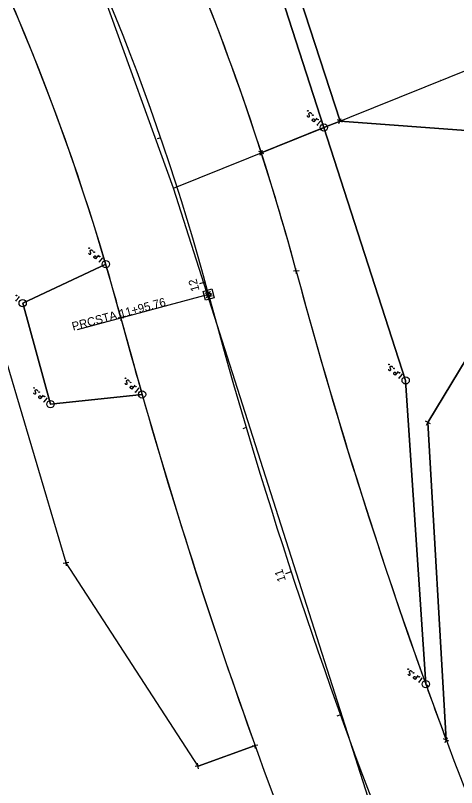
# Model space of a CAD drawing. Extents: x 2392034 to 2394211, y 184331 to 186655.
# Drawn here: x 2392791 to 2392936.9, y 185125.1 to 185380.6 of the extents above; entities that cross this region are included whole.
import ezdxf

# ---------------------------------------------------------------- set-up
doc = ezdxf.new("R2010")
doc.units = 0
for name, color, linetype in [('V-ROAD-SIGN', 7, 'Continuous'), ('V-SITE-MAIL', 7, 'Continuous'), ('V-SITE-MISC', 7, 'Continuous'), ('V-SURV-ANNO', 7, 'Continuous'), ('V-TOPO-ANNO', 7, 'Continuous'), ('V-TOPO-TINN', 7, 'Continuous'), ('V-TOPO-USER', 7, 'Continuous'), ('V-TOPO-WSHD', 7, 'Continuous'), ('V-UTIL-NGAS-STRC', 7, 'Continuous'), ('V-UTIL-SSWR-STRC', 7, 'Continuous'), ('V-UTIL-STRM-STRC', 7, 'Continuous')]:
    doc.layers.add(name, color=color, linetype=linetype)

msp = doc.modelspace()

# ---------------------------------------------------------------- linework, layer by layer
for p, q in [((2392854.78, 185288.58), (2392854.78, 185288.58)), ((2392854.78, 185288.58), (2392854.78, 185288.58)), ((2392854.87, 185288.23), (2392854.87, 185288.23)), ((2392855.06, 185287.51), (2392855.06, 185287.51)), ((2392861.73, 185263.39), (2392861.73, 185263.39)), ((2392832.87, 185255.19), (2392832.87, 185255.19))]:
    msp.add_line(p, q)
at = {"layer": 'Defpoints'}
for centre in [(2392885.39, 185367.2), (2392931.57, 185359.02), (2392903.47, 185311.11), (2392802.61, 185251.97), (2392807.77, 185199.41)]:
    msp.add_circle(centre, 0.05, dxfattribs=at)
at = {"layer": 'V-ROAD-SIGN'}
for centre, radius, start, end in [((2392082.2, 185080.9), 830, 15.02013, 45.41914), ((2392082.2, 185080.9), 770, 15.02013, 44.49359), ((2394545.08, 185741.75), 1720, 195.02013, 207.9775), ((2394545.08, 185741.75), 1780, 195.02013, 207.9775)]:
    msp.add_arc(centre, radius, start, end, dxfattribs=at)
at = {"layer": 'V-SITE-MAIL'}
for centre, radius, start, end in [((2392082.2, 185080.9), 800, 15.02013, 44.49359), ((2394545.08, 185741.75), 1750, 195.02013, 207.9775)]:
    msp.add_arc(centre, radius, start, end, dxfattribs=at)
at = {"layer": 'V-SITE-MISC'}
msp.add_line((2392854.87, 185288.23), (2392811.41, 185276.56), dxfattribs=at)
msp.add_circle((2392854.87, 185288.23), 0.6, dxfattribs=at)
at = {"layer": 'V-SURV-ANNO'}
for p, q in [((2392839.05, 185340.1), (2392837.92, 185339.71)), ((2392853.76, 185292.32), (2392851.83, 185291.79)), ((2392867.31, 185244.19), (2392866.16, 185243.85)), ((2392882.21, 185196.46), (2392880.31, 185195.84)), ((2392898.46, 185149.18), (2392897.33, 185148.77))]:
    msp.add_line(p, q, dxfattribs=at)
at = {"layer": 'V-TOPO-ANNO'}
for p, q in [((2392843.3, 185323.45), (2392806.01, 185426.43)), ((2392843.3, 185323.45), (2392806.01, 185426.43)), ((2392843.3, 185323.45), (2392979.31, 185378.26)), ((2392843.3, 185323.45), (2392979.31, 185378.26)), ((2392921.32, 185078.99), (2392843.3, 185323.45))]:
    msp.add_line(p, q, dxfattribs=at)
at = {"layer": 'V-TOPO-TINN'}
msp.add_line((2392854.87, 185288.23), (2392854.87, 185288.23), dxfattribs=at)
for points in [[(2392887.45, 185347.41), (2392887.45, 185347.38), (2392887.46, 185347.34), (2392887.51, 185347.24), (2392887.59, 185347.14), (2392887.65, 185347.08), (2392887.68, 185347.06), (2392887.81, 185347), (2392887.95, 185346.97), (2392888.08, 185347), (2392888.16, 185347.06), (2392888.21, 185347.12), (2392888.26, 185347.21), (2392888.25, 185347.33), (2392888.04, 185348.02), (2392888.03, 185348.09), (2392888.05, 185348.14), (2392888.08, 185348.21), (2392888.13, 185348.27), (2392888.19, 185348.32), (2392888.23, 185348.35), (2392888.29, 185348.39), (2392888.34, 185348.41), (2392888.38, 185348.42), (2392888.43, 185348.43), (2392888.47, 185348.43), (2392888.52, 185348.42), (2392888.56, 185348.41), (2392888.64, 185348.35), (2392888.76, 185348.25), (2392888.81, 185348.16), (2392888.86, 185348), (2392888.88, 185347.89)], [(2392887.67, 185348.9), (2392887.63, 185348.94), (2392887.63, 185348.98), (2392887.63, 185349.04), (2392887.67, 185349.09), (2392887.73, 185349.1), (2392887.77, 185349.1), (2392887.82, 185349.07), (2392887.82, 185349.03), (2392887.82, 185348.97), (2392887.77, 185348.92), (2392887.72, 185348.9), (2392887.67, 185348.9)], [(2392889.32, 185347.47), (2392889.28, 185347.51), (2392889.27, 185347.55), (2392889.28, 185347.61), (2392889.32, 185347.66), (2392889.38, 185347.67), (2392889.42, 185347.67), (2392889.46, 185347.63), (2392889.47, 185347.59), (2392889.46, 185347.53), (2392889.42, 185347.48), (2392889.36, 185347.47), (2392889.32, 185347.47)], [(2392890.7, 185346.55), (2392889.65, 185345.35), (2392889.25, 185345.7), (2392889.22, 185345.74), (2392889.18, 185345.81), (2392889.17, 185345.85), (2392889.16, 185345.89), (2392889.17, 185345.97), (2392889.18, 185346.04), (2392889.23, 185346.13), (2392889.33, 185346.24), (2392889.37, 185346.27), (2392889.44, 185346.32), (2392889.53, 185346.35), (2392889.59, 185346.35), (2392889.63, 185346.35), (2392889.69, 185346.33), (2392889.76, 185346.28), (2392890.16, 185345.94)], [(2392891.88, 185345.53), (2392890.83, 185344.32)], [(2392891.02, 185345.99), (2392890.98, 185346.03), (2392890.97, 185346.07), (2392890.98, 185346.13), (2392891.02, 185346.18), (2392891.07, 185346.2), (2392891.12, 185346.19), (2392891.16, 185346.16), (2392891.17, 185346.12), (2392891.16, 185346.06), (2392891.12, 185346.01), (2392891.06, 185345.99), (2392891.02, 185345.99)], [(2392892.01, 185345.41), (2392891.75, 185345.64)], [(2392890.96, 185344.2), (2392890.7, 185344.44)], [(2392815.16, 185301.96), (2392815.17, 185301.93), (2392815.18, 185301.89), (2392815.23, 185301.8), (2392815.31, 185301.7), (2392815.38, 185301.65), (2392815.4, 185301.63), (2392815.54, 185301.57), (2392815.68, 185301.55), (2392815.8, 185301.58), (2392815.88, 185301.65), (2392815.93, 185301.7), (2392815.98, 185301.8), (2392815.96, 185301.92), (2392815.72, 185302.59), (2392815.71, 185302.67), (2392815.73, 185302.72), (2392815.76, 185302.79), (2392815.8, 185302.85), (2392815.86, 185302.91), (2392815.9, 185302.94), (2392815.96, 185302.97), (2392816.01, 185303), (2392816.05, 185303.01), (2392816.1, 185303.02), (2392816.14, 185303.02), (2392816.19, 185303.02), (2392816.22, 185303), (2392816.31, 185302.95), (2392816.43, 185302.86), (2392816.49, 185302.77), (2392816.55, 185302.62), (2392816.57, 185302.5)], [(2392815.32, 185303.47), (2392815.28, 185303.5), (2392815.27, 185303.54), (2392815.27, 185303.6), (2392815.31, 185303.65), (2392815.37, 185303.67), (2392815.41, 185303.67), (2392815.45, 185303.63), (2392815.46, 185303.59), (2392815.46, 185303.53), (2392815.42, 185303.48), (2392815.36, 185303.46), (2392815.32, 185303.47)], [(2392817.03, 185302.1), (2392816.98, 185302.14), (2392816.97, 185302.18), (2392816.98, 185302.24), (2392817.02, 185302.29), (2392817.07, 185302.31), (2392817.12, 185302.31), (2392817.16, 185302.27), (2392817.17, 185302.23), (2392817.16, 185302.17), (2392817.12, 185302.12), (2392817.07, 185302.1), (2392817.03, 185302.1)], [(2392818.44, 185301.25), (2392817.44, 185300), (2392817.03, 185300.33), (2392817, 185300.37), (2392816.95, 185300.44), (2392816.94, 185300.48), (2392816.93, 185300.52), (2392816.94, 185300.6), (2392816.95, 185300.67), (2392817, 185300.76), (2392817.09, 185300.88), (2392817.13, 185300.91), (2392817.19, 185300.95), (2392817.28, 185301), (2392817.34, 185301), (2392817.38, 185301), (2392817.44, 185300.98), (2392817.52, 185300.94), (2392817.93, 185300.61)], [(2392818.81, 185298.91), (2392818.53, 185299.13)], [(2392819.67, 185300.27), (2392818.67, 185299.02)], [(2392818.78, 185300.7), (2392818.74, 185300.74), (2392818.73, 185300.78), (2392818.74, 185300.84), (2392818.78, 185300.88), (2392818.83, 185300.9), (2392818.87, 185300.9), (2392818.92, 185300.87), (2392818.93, 185300.83), (2392818.92, 185300.77), (2392818.88, 185300.72), (2392818.82, 185300.7), (2392818.78, 185300.7)], [(2392819.8, 185300.16), (2392819.53, 185300.38)], [(2392853.82, 185286.38), (2392853.03, 185289.27), (2392855.92, 185290.07), (2392856.72, 185287.18), (2392853.82, 185286.38)], [(2392856.03, 185287.78), (2392854.1, 185287.25), (2392855.84, 185288.49), (2392853.71, 185288.67), (2392855.64, 185289.2)], [(2392791.32, 185286.01), (2392791.05, 185286.23)], [(2392792.19, 185287.37), (2392791.18, 185286.12)], [(2392791.31, 185287.8), (2392791.27, 185287.84), (2392791.26, 185287.88), (2392791.26, 185287.94), (2392791.3, 185287.99), (2392791.36, 185288.01), (2392791.4, 185288.01), (2392791.45, 185287.97), (2392791.46, 185287.93), (2392791.45, 185287.87), (2392791.41, 185287.82), (2392791.35, 185287.8), (2392791.31, 185287.8)], [(2392792.33, 185287.26), (2392792.05, 185287.48)], [(2392914.31, 185263.5), (2392914.31, 185263.47), (2392914.32, 185263.43), (2392914.38, 185263.33), (2392914.46, 185263.24), (2392914.52, 185263.18), (2392914.55, 185263.16), (2392914.69, 185263.1), (2392914.83, 185263.09), (2392914.95, 185263.12), (2392915.03, 185263.18), (2392915.08, 185263.24), (2392915.12, 185263.34), (2392915.11, 185263.46), (2392914.87, 185264.13), (2392914.86, 185264.21), (2392914.87, 185264.26), (2392914.9, 185264.33), (2392914.95, 185264.39), (2392915.01, 185264.44), (2392915.05, 185264.48), (2392915.1, 185264.51), (2392915.15, 185264.54), (2392915.19, 185264.55), (2392915.24, 185264.56), (2392915.28, 185264.56), (2392915.33, 185264.55), (2392915.37, 185264.54), (2392915.45, 185264.49), (2392915.57, 185264.4), (2392915.63, 185264.31), (2392915.69, 185264.16), (2392915.71, 185264.04)], [(2392914.46, 185265), (2392914.42, 185265.04), (2392914.41, 185265.08), (2392914.42, 185265.14), (2392914.46, 185265.19), (2392914.51, 185265.21), (2392914.55, 185265.21), (2392914.6, 185265.17), (2392914.61, 185265.13), (2392914.6, 185265.07), (2392914.56, 185265.02), (2392914.51, 185265), (2392914.46, 185265)], [(2392916.17, 185263.65), (2392916.13, 185263.68), (2392916.12, 185263.72), (2392916.12, 185263.78), (2392916.16, 185263.83), (2392916.22, 185263.85), (2392916.26, 185263.85), (2392916.31, 185263.81), (2392916.32, 185263.77), (2392916.31, 185263.71), (2392916.27, 185263.66), (2392916.21, 185263.64), (2392916.17, 185263.65)], [(2392827.36, 185260.44), (2392827.32, 185260.47), (2392827.31, 185260.51), (2392827.31, 185260.57), (2392827.35, 185260.62), (2392827.41, 185260.64), (2392827.45, 185260.64), (2392827.49, 185260.6), (2392827.5, 185260.56), (2392827.5, 185260.5), (2392827.46, 185260.45), (2392827.4, 185260.43), (2392827.36, 185260.44)], [(2392917.59, 185262.79), (2392916.6, 185261.54), (2392916.18, 185261.87), (2392916.15, 185261.91), (2392916.1, 185261.98), (2392916.09, 185262.02), (2392916.08, 185262.06), (2392916.09, 185262.14), (2392916.1, 185262.21), (2392916.14, 185262.3), (2392916.24, 185262.42), (2392916.28, 185262.45), (2392916.34, 185262.5), (2392916.43, 185262.54), (2392916.49, 185262.54), (2392916.53, 185262.54), (2392916.59, 185262.52), (2392916.67, 185262.48), (2392917.08, 185262.15)], [(2392917.96, 185260.45), (2392917.68, 185260.67)], [(2392918.82, 185261.82), (2392917.82, 185260.56)], [(2392917.93, 185262.25), (2392917.89, 185262.28), (2392917.88, 185262.32), (2392917.88, 185262.38), (2392917.92, 185262.43), (2392917.98, 185262.45), (2392918.02, 185262.45), (2392918.07, 185262.41), (2392918.08, 185262.37), (2392918.07, 185262.31), (2392918.03, 185262.26), (2392917.97, 185262.25), (2392917.93, 185262.25)], [(2392918.95, 185261.71), (2392918.68, 185261.93)], [(2392827.19, 185258.93), (2392827.19, 185258.9), (2392827.2, 185258.86), (2392827.25, 185258.77), (2392827.33, 185258.67), (2392827.4, 185258.62), (2392827.42, 185258.6), (2392827.56, 185258.53), (2392827.7, 185258.52), (2392827.83, 185258.55), (2392827.91, 185258.61), (2392827.95, 185258.67), (2392828, 185258.76), (2392827.99, 185258.88), (2392827.76, 185259.56), (2392827.74, 185259.63), (2392827.76, 185259.69), (2392827.79, 185259.76), (2392827.84, 185259.82), (2392827.89, 185259.87), (2392827.93, 185259.9), (2392827.99, 185259.94), (2392828.04, 185259.96), (2392828.08, 185259.98), (2392828.13, 185259.99), (2392828.17, 185259.98), (2392828.22, 185259.98), (2392828.26, 185259.97), (2392828.34, 185259.91), (2392828.46, 185259.82), (2392828.52, 185259.73), (2392828.58, 185259.57), (2392828.6, 185259.46)], [(2392830.46, 185258.19), (2392829.45, 185256.95), (2392829.04, 185257.28), (2392829.01, 185257.32), (2392828.96, 185257.39), (2392828.95, 185257.43), (2392828.94, 185257.47), (2392828.95, 185257.55), (2392828.96, 185257.62), (2392829.01, 185257.71), (2392829.1, 185257.83), (2392829.14, 185257.86), (2392829.21, 185257.91), (2392829.3, 185257.95), (2392829.36, 185257.95), (2392829.4, 185257.95), (2392829.46, 185257.93), (2392829.53, 185257.89), (2392829.94, 185257.55)], [(2392829.05, 185259.06), (2392829.01, 185259.09), (2392829, 185259.13), (2392829.01, 185259.19), (2392829.05, 185259.24), (2392829.1, 185259.26), (2392829.14, 185259.26), (2392829.19, 185259.22), (2392829.2, 185259.18), (2392829.19, 185259.12), (2392829.15, 185259.07), (2392829.09, 185259.06), (2392829.05, 185259.06)], [(2392830.8, 185257.64), (2392830.75, 185257.67), (2392830.74, 185257.71), (2392830.75, 185257.77), (2392830.79, 185257.82), (2392830.85, 185257.84), (2392830.89, 185257.84), (2392830.93, 185257.8), (2392830.94, 185257.76), (2392830.93, 185257.7), (2392830.9, 185257.66), (2392830.84, 185257.64), (2392830.8, 185257.64)], [(2392796.94, 185255.73), (2392796.94, 185255.69), (2392796.95, 185255.65), (2392797, 185255.56), (2392797.08, 185255.46), (2392797.15, 185255.41), (2392797.17, 185255.39), (2392797.31, 185255.33), (2392797.45, 185255.31), (2392797.57, 185255.34), (2392797.65, 185255.4), (2392797.7, 185255.46), (2392797.75, 185255.55), (2392797.73, 185255.67), (2392797.5, 185256.35), (2392797.49, 185256.43), (2392797.51, 185256.48), (2392797.54, 185256.55), (2392797.59, 185256.61), (2392797.64, 185256.66), (2392797.68, 185256.69), (2392797.74, 185256.73), (2392797.79, 185256.75), (2392797.83, 185256.77), (2392797.88, 185256.78), (2392797.92, 185256.77), (2392797.97, 185256.77), (2392798.01, 185256.75), (2392798.09, 185256.7), (2392798.21, 185256.6), (2392798.27, 185256.52), (2392798.33, 185256.36), (2392798.35, 185256.25)], [(2392797.11, 185257.23), (2392797.07, 185257.26), (2392797.06, 185257.3), (2392797.06, 185257.36), (2392797.1, 185257.41), (2392797.16, 185257.43), (2392797.2, 185257.43), (2392797.25, 185257.39), (2392797.26, 185257.35), (2392797.25, 185257.29), (2392797.21, 185257.24), (2392797.15, 185257.23), (2392797.11, 185257.23)], [(2392798.8, 185255.84), (2392798.76, 185255.88), (2392798.75, 185255.92), (2392798.75, 185255.98), (2392798.79, 185256.03), (2392798.85, 185256.05), (2392798.89, 185256.05), (2392798.93, 185256.01), (2392798.94, 185255.97), (2392798.94, 185255.91), (2392798.9, 185255.86), (2392798.84, 185255.84), (2392798.8, 185255.84)], [(2392830.8, 185255.85), (2392830.53, 185256.07)], [(2392831.68, 185257.2), (2392830.67, 185255.96)], [(2392831.81, 185257.09), (2392831.54, 185257.31)], [(2392800.21, 185254.97), (2392799.19, 185253.73), (2392798.78, 185254.07), (2392798.75, 185254.11), (2392798.7, 185254.18), (2392798.69, 185254.22), (2392798.69, 185254.26), (2392798.69, 185254.34), (2392798.71, 185254.41), (2392798.75, 185254.5), (2392798.85, 185254.62), (2392798.89, 185254.65), (2392798.95, 185254.69), (2392799.04, 185254.73), (2392799.1, 185254.73), (2392799.14, 185254.73), (2392799.2, 185254.72), (2392799.28, 185254.67), (2392799.69, 185254.34)], [(2392800.54, 185252.63), (2392800.27, 185252.85)], [(2392801.42, 185253.98), (2392800.4, 185252.74)], [(2392800.54, 185254.42), (2392800.5, 185254.46), (2392800.49, 185254.5), (2392800.49, 185254.56), (2392800.53, 185254.6), (2392800.59, 185254.62), (2392800.63, 185254.62), (2392800.67, 185254.59), (2392800.68, 185254.55), (2392800.68, 185254.49), (2392800.64, 185254.44), (2392800.58, 185254.42), (2392800.54, 185254.42)], [(2392801.55, 185253.87), (2392801.28, 185254.09)], [(2392920.76, 185162.68), (2392920.77, 185162.65), (2392920.78, 185162.61), (2392920.84, 185162.52), (2392920.92, 185162.43), (2392921, 185162.38), (2392921.02, 185162.36), (2392921.16, 185162.31), (2392921.3, 185162.3), (2392921.42, 185162.34), (2392921.5, 185162.41), (2392921.54, 185162.47), (2392921.58, 185162.56), (2392921.56, 185162.68), (2392921.29, 185163.34), (2392921.27, 185163.42), (2392921.28, 185163.47), (2392921.31, 185163.54), (2392921.35, 185163.61), (2392921.4, 185163.66), (2392921.44, 185163.7), (2392921.5, 185163.74), (2392921.54, 185163.76), (2392921.58, 185163.78), (2392921.63, 185163.79), (2392921.67, 185163.8), (2392921.72, 185163.79), (2392921.76, 185163.78), (2392921.85, 185163.73), (2392921.97, 185163.65), (2392922.04, 185163.57), (2392922.1, 185163.41), (2392922.13, 185163.3)], [(2392920.83, 185164.19), (2392920.79, 185164.22), (2392920.77, 185164.26), (2392920.77, 185164.32), (2392920.81, 185164.37), (2392920.87, 185164.39), (2392920.91, 185164.4), (2392920.95, 185164.36), (2392920.97, 185164.32), (2392920.96, 185164.26), (2392920.93, 185164.21), (2392920.87, 185164.19), (2392920.83, 185164.19)], [(2392922.61, 185162.93), (2392922.57, 185162.96), (2392922.56, 185163), (2392922.56, 185163.06), (2392922.59, 185163.11), (2392922.65, 185163.14), (2392922.69, 185163.14), (2392922.74, 185163.11), (2392922.75, 185163.07), (2392922.75, 185163.01), (2392922.71, 185162.95), (2392922.66, 185162.93), (2392922.61, 185162.93)], [(2392924.08, 185162.16), (2392923.16, 185160.85), (2392922.72, 185161.16), (2392922.69, 185161.2), (2392922.64, 185161.26), (2392922.63, 185161.3), (2392922.61, 185161.34), (2392922.61, 185161.42), (2392922.62, 185161.49), (2392922.66, 185161.59), (2392922.75, 185161.71), (2392922.79, 185161.74), (2392922.85, 185161.79), (2392922.94, 185161.84), (2392922.99, 185161.84), (2392923.04, 185161.85), (2392923.1, 185161.84), (2392923.17, 185161.79), (2392923.61, 185161.49)], [(2392924.45, 185161.63), (2392924.41, 185161.67), (2392924.39, 185161.71), (2392924.4, 185161.77), (2392924.43, 185161.82), (2392924.49, 185161.84), (2392924.53, 185161.84), (2392924.57, 185161.81), (2392924.59, 185161.77), (2392924.58, 185161.71), (2392924.55, 185161.66), (2392924.49, 185161.64), (2392924.45, 185161.63)], [(2392925.36, 185161.26), (2392924.44, 185159.95)], [(2392925.5, 185161.15), (2392925.21, 185161.36)], [(2392924.58, 185159.85), (2392924.29, 185160.05)]]:
    msp.add_lwpolyline(points, dxfattribs=at)
for centre in [(2392893.01, 185343.48), (2392820.88, 185298.28), (2392793.4, 185285.37), (2392920.04, 185259.83), (2392832.87, 185255.19), (2392802.61, 185251.97), (2392926.69, 185159.34)]:
    msp.add_circle(centre, 1.2, dxfattribs=at)
at = {"layer": 'V-TOPO-USER'}
for p, q in [((2392893.01, 185343.48), (2392872.2, 185407.9)), ((2392920.04, 185259.83), (2392893.01, 185343.48)), ((2392793.4, 185285.37), (2392820.88, 185298.28)), ((2392802.61, 185251.97), (2392793.4, 185285.37)), ((2392926.69, 185159.34), (2392920.04, 185259.83)), ((2392832.87, 185255.19), (2392802.61, 185251.97))]:
    msp.add_line(p, q, dxfattribs=at)
at = {"layer": 'V-TOPO-WSHD'}
for p, q in [((2392898.34, 185345.63), (2392872.35, 185425.45)), ((2392964.78, 185340.62), (2392898.34, 185345.63)), ((2392927.38, 185245.87), (2392975.28, 185325.62)), ((2392807.77, 185199.41), (2392772.83, 185317.42)), ((2392933.45, 185140.88), (2392927.38, 185245.87)), ((2392851.42, 185132.25), (2392807.77, 185199.41)), ((2392851.42, 185132.25), (2392870.24, 185139.02))]:
    msp.add_line(p, q, dxfattribs=at)
at = {"layer": 'V-UTIL-NGAS-STRC'}
for p, q in [((2392899.2, 185345.23), (2392897.49, 185346.03)), ((2392897.94, 185344.78), (2392898.75, 185346.48)), ((2392873.15, 185334.72), (2392871.46, 185335.56)), ((2392871.89, 185334.29), (2392872.73, 185335.99)), ((2392883.93, 185295.06), (2392883.77, 185296.94)), ((2392884.79, 185296.08), (2392882.91, 185295.92)), ((2392825.98, 185279.51), (2392825.82, 185281.39)), ((2392826.84, 185280.53), (2392824.96, 185280.37)), ((2392928.21, 185245.43), (2392926.55, 185246.31)), ((2392926.94, 185245.04), (2392927.82, 185246.7)), ((2392808.7, 185199.53), (2392806.83, 185199.29)), ((2392807.89, 185198.48), (2392807.65, 185200.35)), ((2392934.31, 185140.48), (2392932.6, 185141.28)), ((2392933.05, 185140.03), (2392933.86, 185141.73)), ((2392871.17, 185139.18), (2392869.31, 185138.86)), ((2392870.4, 185138.09), (2392870.08, 185139.95)), ((2392851.58, 185131.32), (2392851.26, 185133.18)), ((2392852.35, 185132.41), (2392850.49, 185132.09))]:
    msp.add_line(p, q, dxfattribs=at)
at = {"layer": 'V-UTIL-SSWR-STRC'}
for p, q in [((2392872.35, 185425.45), (2392898.34, 185345.63)), ((2392893.01, 185343.48), (2392872.2, 185407.9)), ((2392893.01, 185343.48), (2392872.2, 185407.9)), ((2392898.34, 185345.63), (2392964.78, 185340.62)), ((2392893.01, 185343.48), (2392872.31, 185335.14)), ((2392872.31, 185335.14), (2392893.01, 185343.48)), ((2392920.04, 185259.83), (2392893.01, 185343.48)), ((2392920.04, 185259.83), (2392893.01, 185343.48)), ((2392975.28, 185325.62), (2392927.38, 185245.87)), ((2392793.4, 185285.37), (2392820.88, 185298.28)), ((2392802.61, 185251.97), (2392793.4, 185285.37)), ((2392926.69, 185159.34), (2392920.04, 185259.83)), ((2392926.69, 185159.34), (2392920.04, 185259.83)), ((2392832.87, 185255.19), (2392802.61, 185251.97)), ((2392927.38, 185245.87), (2392933.45, 185140.88))]:
    msp.add_line(p, q, dxfattribs=at)
for centre, radius, start, end in [((2392082.2, 185080.9), 830, 17.83729, 26.06673), ((2392082.2, 185080.9), 830, 15.02013, 17.83729), ((2392082.2, 185080.9), 770, 15.02013, 16.39806), ((2394545.08, 185741.75), 1720, 195.02013, 199.79239), ((2394545.08, 185741.75), 1720, 195.02013, 199.79239), ((2394545.08, 185741.75), 1780, 195.02013, 195.86354)]:
    msp.add_arc(centre, radius, start, end, dxfattribs=at)
at = {"layer": 'V-UTIL-STRM-STRC'}
for p, q in [((2392898.34, 185345.63), (2392872.35, 185425.45)), ((2392872.2, 185407.9), (2392893.01, 185343.48)), ((2392872.2, 185407.9), (2392893.01, 185343.48)), ((2392898.34, 185345.63), (2392893.01, 185343.48)), ((2392893.01, 185343.48), (2392898.34, 185345.63)), ((2392964.78, 185340.62), (2392898.34, 185345.63)), ((2392893.01, 185343.48), (2392920.04, 185259.83)), ((2392893.01, 185343.48), (2392920.04, 185259.83)), ((2392927.38, 185245.87), (2392975.28, 185325.62)), ((2392807.77, 185199.41), (2392772.83, 185317.42)), ((2392820.88, 185298.28), (2392793.4, 185285.37)), ((2392793.4, 185285.37), (2392802.61, 185251.97)), ((2392920.04, 185259.83), (2392926.69, 185159.34)), ((2392920.04, 185259.83), (2392926.69, 185159.34)), ((2392802.61, 185251.97), (2392832.87, 185255.19)), ((2392933.45, 185140.88), (2392927.38, 185245.87)), ((2392851.42, 185132.25), (2392807.77, 185199.41)), ((2392926.69, 185159.34), (2392927.68, 185158.52)), ((2392870.24, 185139.02), (2392851.42, 185132.25))]:
    msp.add_line(p, q, dxfattribs=at)
for centre, radius, start, end in [((2392082.2, 185080.9), 770, 16.39806, 33.9449), ((2392082.2, 185080.9), 830, 17.83729, 26.06673), ((2392082.2, 185080.9), 830, 15.02013, 17.83729), ((2394545.08, 185741.75), 1720, 195.02013, 199.79239), ((2394545.08, 185741.75), 1780, 195.86354, 199.79239), ((2394545.08, 185741.75), 1720, 199.79239, 200.4472), ((2394545.08, 185741.75), 1720, 199.79239, 200.4472)]:
    msp.add_arc(centre, radius, start, end, dxfattribs=at)

# ---------------------------------------------------------------- texts
at = {"layer": 'V-SITE-MISC'}
for s, p in [('11+95.76', (2392825.76, 185280.45)), ('PRC', (2392810.09, 185276.25)), (' STA. ', (2392816.76, 185278.04))]:
    msp.add_text(s, height=2.8, rotation=15.0201, dxfattribs=at).set_placement(p)
at = {"layer": 'V-SURV-ANNO'}
for s, rotation, p in [('12', 105.3238, (2392851.91, 185289.64)), ('11', 108.1554, (2392880.49, 185193.68))]:
    msp.add_text(s, height=2.8, rotation=rotation, dxfattribs=at).set_placement(p)

doc.saveas('drawing.dxf')
